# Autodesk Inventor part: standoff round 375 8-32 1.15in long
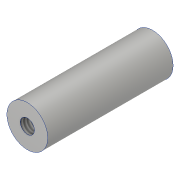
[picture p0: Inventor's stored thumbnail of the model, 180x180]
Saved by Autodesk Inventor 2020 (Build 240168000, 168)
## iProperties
Created: 2017-09
Part Number: standoff round 375 8-32 1.15in long
Material: Aluminum 6061
Document SubType Name: Modeling
Designer: woodk
Density: 2.7 g/cm^3
Appearance: Aluminum - Flat
Mass: 4.94436 g
Surface Area: 13.0247 cm^2
Volume: 1.83124 cm^3
Vendor: LER
Author: woodk
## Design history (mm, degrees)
sketch "Sketch1"
  geometry: C1 r 4.763 at (0, 0); 1 further point
  constraints: 1 centre point, 1 coincident
  dimensions: "d0" = 9.525 diameter of C1
extrude "Extrusion1" new body sketch "Sketch1" distance "d2" = 29.21; taper "d3" = 0 deg
sketch "Sketch2"
  geometry: 2 further points
  constraints: 1 coincident
hole "Hole1" sketch "Sketch2" at (0, 0) diameter "d4" = 3.302; stored, may be unused: countersink angle "d8" = 82 deg, drill point angle "d10" = 118 deg; dims "d5" = 8.3312, "d6" = 9.525, "d7" = 6.35, "d9" = 12.2936
body "Solid1"
